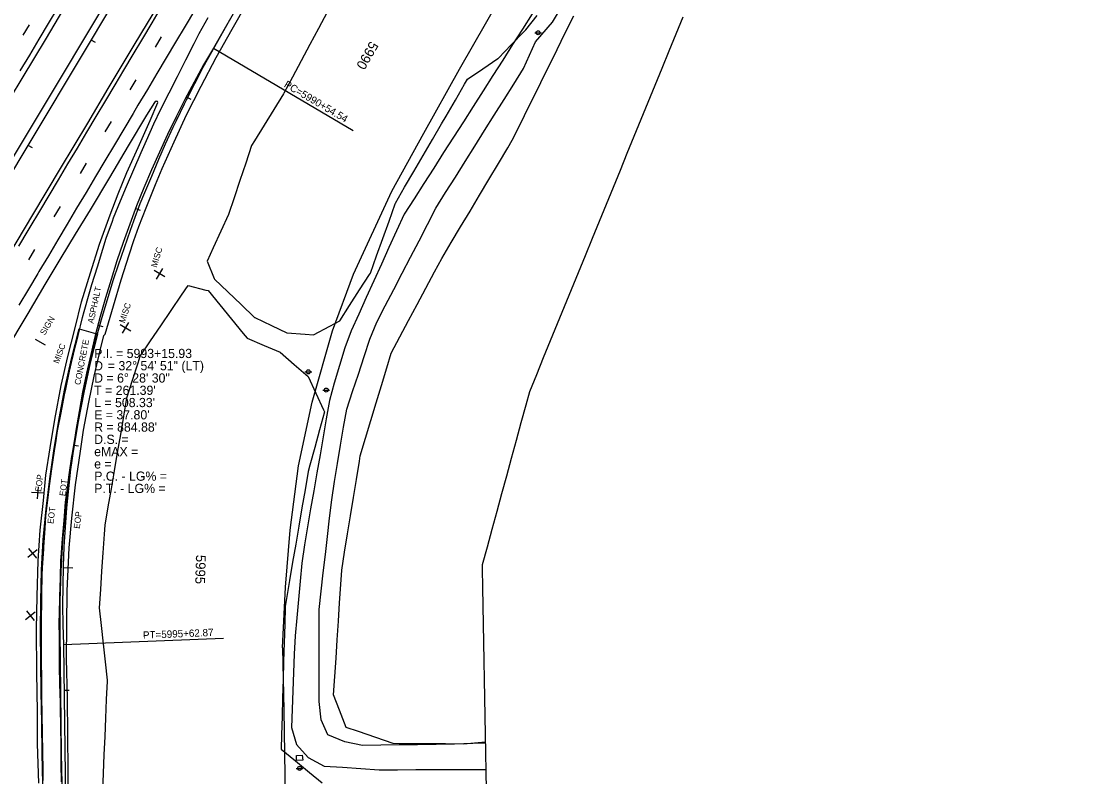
# Model space of a CAD drawing. Extents: x 2132221 to 2141942, y 535736 to 547298.
# Drawn here: x 2138929 to 2139793, y 541568 to 542184 of the extents above; entities that cross this region are included whole.
import ezdxf

# ---------------------------------------------------------------- set-up
doc = ezdxf.new("R2010")
doc.units = 0
for name, color, linetype in [('RD_EX_BldgApp', 7, 'Continuous'), ('RD_EX_BldgApp_txCode', 7, 'Continuous'), ('RD_EX_Conc', 7, 'Continuous'), ('RD_EX_Conc_txCode', 7, 'Continuous'), ('RD_EX_Driveway', 7, 'Continuous'), ('RD_EX_Fence_Other', 7, 'Continuous'), ('RD_EX_GuardRail', 7, 'Continuous'), ('RD_EX_Misc', 7, 'Continuous'), ('RD_EX_Misc_txCode', 7, 'Continuous'), ('RD_EX_Road', 7, 'Continuous'), ('RD_EX_Road_txCode', 7, 'Continuous'), ('RD_EX_SU_Pole', 7, 'Continuous'), ('RD_EX_VEG', 7, 'Continuous'), ('RD_HC_Cl', 7, 'Continuous'), ('RD_HC_Data', 7, 'Continuous'), ('RD_HC_Data_Tic', 7, 'Continuous'), ('RD_HC_TX_Sta50', 7, 'Continuous'), ('TOPO_E_TLIML-Line', 7, 'Continuous')]:
    doc.layers.add(name, color=color, linetype=linetype)

msp = doc.modelspace()

# ---------------------------------------------------------------- linework, layer by layer
at = {"layer": 'RD_EX_BldgApp'}
msp.add_line((2138939.91, 541924.37), (2138947.96, 541919.89), dxfattribs=at)
at = {"layer": 'RD_EX_Conc'}
for points in [[(2138964.17, 541884.13), (2138969.59, 541908.45), (2138975.68, 541932.7), (2138990.91, 541928.6)], [(2138979.79, 541880.98), (2138985.1, 541905.1), (2138990.91, 541928.6)], [(2138946.05, 541561.75), (2138945.51, 541586.82), (2138945.34, 541611.6), (2138944.81, 541636.66), (2138944.62, 541661.19), (2138944.29, 541686.45), (2138944.44, 541711.23), (2138945.21, 541736.04), (2138946.56, 541760.92), (2138948.83, 541786.03), (2138951.88, 541810.52), (2138955.41, 541835.19), (2138959.43, 541859.75), (2138964.17, 541884.13)], [(2138962.18, 541536.91), (2138961.81, 541562.08), (2138961.45, 541586.73), (2138961.09, 541611.67), (2138960.87, 541636.68), (2138960.43, 541661.54), (2138960.22, 541686.19), (2138960.39, 541710.97), (2138961.07, 541735.39), (2138962.56, 541759.82), (2138964.6, 541783.95), (2138967.59, 541808.74), (2138971.09, 541833.05), (2138975.3, 541857.21), (2138979.79, 541880.98)]]:
    msp.add_lwpolyline(points, dxfattribs=at)
at = {"layer": 'RD_EX_Driveway'}
for points in [[(2139307.02, 541595.19), (2139296.59, 541594.73), (2139281.59, 541594.29), (2139266.6, 541594.06), (2139251.6, 541593.84), (2139236.6, 541593.62), (2139221.6, 541593.39), (2139206.6, 541593.17), (2139192.23, 541596.25), (2139178.33, 541601.91), (2139172.94, 541614.14), (2139171.47, 541629.04), (2139171.47, 541644.04), (2139171.47, 541659.04), (2139171.47, 541674.04), (2139171.47, 541689.04), (2139171.47, 541704.04), (2139173.02, 541718.95), (2139174.71, 541733.86), (2139176.39, 541748.76), (2139178.07, 541763.67), (2139179.76, 541778.57), (2139181.57, 541793.46), (2139183.97, 541808.27), (2139186.38, 541823.07), (2139188.78, 541837.88), (2139191.18, 541852.68), (2139193.97, 541867.4), (2139198.62, 541881.66), (2139203.28, 541895.92), (2139207.94, 541910.18), (2139212.59, 541924.43), (2139218.36, 541938.21), (2139225.23, 541951.5), (2139232.11, 541964.78), (2139238.98, 541978.07), (2139245.85, 541991.36), (2139252.73, 542004.65), (2139259.6, 542017.94), (2139266.48, 542031.23), (2139274.4, 542043.86), (2139282.33, 542056.49), (2139290.26, 542069.12), (2139298.19, 542081.75), (2139306.12, 542094.38), (2139314.05, 542107.01), (2139321.98, 542119.64), (2139329.91, 542132.26), (2139337.88, 542144.97), (2139347.77, 542166.84), (2139361.62, 542182.78), (2139369.1, 542195.67)], [(2139345.05, 542189.57), (2139337.02, 542177), (2139328.99, 542164.44), (2139320.96, 542151.87), (2139312.89, 542139.23), (2139304.9, 542126.73), (2139296.87, 542114.16), (2139288.85, 542101.59), (2139280.77, 542088.95), (2139272.79, 542076.46), (2139264.76, 542063.89), (2139256.73, 542051.32), (2139248.7, 542038.75), (2139240.67, 542026.18), (2139234.37, 542012.68), (2139228.21, 541999.09), (2139222.06, 541985.5), (2139215.9, 541971.92), (2139209.74, 541958.33), (2139203.59, 541944.75), (2139197.43, 541931.16), (2139192.2, 541917.22), (2139187.9, 541902.94), (2139183.6, 541888.66), (2139179.7, 541874.28), (2139177.15, 541859.58), (2139174.6, 541844.88), (2139172.04, 541830.1), (2139169.5, 541815.48), (2139166.95, 541800.78), (2139164.4, 541786.08), (2139161.85, 541771.38), (2139159.3, 541756.68), (2139157.11, 541741.94), (2139155.79, 541727.08), (2139154.46, 541712.22), (2139153.14, 541697.36), (2139151.81, 541682.5), (2139151.07, 541667.6), (2139150.49, 541652.69), (2139149.9, 541637.79), (2139149.32, 541622.88), (2139148.74, 541607.97), (2139152.78, 541594.01), (2139162.33, 541583.33), (2139175.41, 541576.48), (2139190.34, 541575.45), (2139205.27, 541574.42), (2139220.2, 541573.47), (2139235.17, 541573.49), (2139250.13, 541573.51), (2139265.1, 541573.52), (2139280.06, 541573.54), (2139295.03, 541573.56), (2139307.41, 541573.57)]]:
    msp.add_lwpolyline(points, dxfattribs=at)
msp.add_lwpolyline([(2139153, 541585.04), (2139157.61, 541585.29), (2139158, 541581.37), (2139152.91, 541580.85)], close=True, dxfattribs=at)
at = {"layer": 'RD_EX_Fence_Other'}
for p, q in [((2139182.15, 541931.16), (2139199.29, 541977.5)), ((2139141.58, 541672.69), (2139143.91, 541722.32))]:
    msp.add_line(p, q, dxfattribs=at)
for points in [[(2139199.29, 541977.5), (2139230.66, 542044.92), (2139256.71, 542092.39), (2139285.74, 542144.4), (2139307.85, 542183.32), (2139338.4, 542236.88), (2139366.99, 542286.98), (2139396.2, 542337.99), (2139425.31, 542387.63), (2139459.61, 542447.78), (2139484.3, 542490.86), (2139507.59, 542531.82), (2139537.21, 542583.28), (2139570.34, 542640.33), (2139599.47, 542691.68), (2139623.24, 542733.3), (2139663.17, 542802.94), (2139685.76, 542843.79), (2139714.19, 542892.36), (2139738.8, 542935.51), (2139769.46, 542989.44), (2139792.81, 543030.29)], [(2139143.91, 541722.32), (2139147.81, 541768.77), (2139154.56, 541821.06), (2139165.57, 541873.11), (2139182.15, 541931.16)], [(2139141.58, 541672.69), (2139142.42, 541621.94), (2139143.3, 541569.08), (2139144.31, 541512.66), (2139145.95, 541449.43), (2139146.66, 541393.38), (2139147.22, 541353.23), (2139147.73, 541294.87), (2139148.66, 541239.78)]]:
    msp.add_lwpolyline(points, dxfattribs=at)
at = {"layer": 'RD_EX_GuardRail'}
msp.add_lwpolyline([(2138851.75, 541955.34), (2138865.25, 541977.82), (2138891.04, 542021.08), (2138921.51, 542071.79), (2138957.23, 542131.41), (2138984.41, 542176.81), (2139016.58, 542230.45), (2139056.94, 542297.59), (2139088.78, 542351.41), (2139113.89, 542392.68), (2139145.32, 542445.41), (2139147.37, 542448.82)], dxfattribs=at)
at = {"layer": 'RD_EX_Misc'}
for p, q in [((2138930.23, 542172.24), (2138935.22, 542180.63)), ((2139037.97, 542162.44), (2139042.97, 542170.82)), ((2139017.31, 542127.5), (2139022.3, 542135.88)), ((2138997.01, 542093.48), (2139002.01, 542101.86)), ((2138976.78, 542059.39), (2138981.77, 542067.78)), ((2138955.46, 542024.23), (2138960.46, 542032.62)), ((2138934.69, 541989.19), (2138939.68, 541997.58)), ((2139045.58, 541975.17), (2139036.99, 541980.29)), ((2139038.73, 541973.43), (2139043.84, 541982.03)), ((2139017.89, 541931.01), (2139009.3, 541936.13)), ((2139011.03, 541929.27), (2139016.15, 541937.87)), ((2138946.99, 541798.79), (2138937.02, 541799.52)), ((2138942.37, 541804.14), (2138941.64, 541794.17)), ((2138933.87, 541746.67), (2138941.64, 541752.96)), ((2138934.61, 541753.7), (2138940.9, 541745.93)), ((2138932.78, 541702.95), (2138939.07, 541695.18)), ((2138932.04, 541695.92), (2138939.81, 541702.21))]:
    msp.add_line(p, q, dxfattribs=at)
for points in [[(2138926.58, 542000.16), (2138934.32, 542013.01), (2138935.95, 542015.73), (2138943.63, 542028.61), (2138951.3, 542041.5), (2138958.98, 542054.39), (2138966.66, 542067.27), (2138974.34, 542080.16), (2138982.01, 542093.04), (2138989.69, 542105.93), (2138997.37, 542118.82), (2139005.05, 542131.7), (2139012.17, 542143.66), (2139019.86, 542156.54), (2139027.55, 542169.42), (2139035.24, 542182.3), (2139042.93, 542195.18)], [(2139069.74, 542192.36), (2139062.07, 542179.47), (2139054.39, 542166.58), (2139046.72, 542153.7), (2139039.05, 542140.81), (2139031.37, 542127.92), (2139023.7, 542115.03), (2139019.77, 542108.44), (2139012.1, 542095.55), (2139004.43, 542082.66), (2138996.75, 542069.77), (2138989.08, 542056.89), (2138981.4, 542044), (2138973.73, 542031.11), (2138966.06, 542018.22), (2138958.38, 542005.33), (2138950.71, 541992.44), (2138943.03, 541979.56), (2138942.08, 541977.95), (2138934.38, 541965.07), (2138926.68, 541952.2)], [(2138927.75, 542143.14), (2138935.45, 542156.01), (2138943.16, 542168.88), (2138950.86, 542181.75), (2138958.57, 542194.62)], [(2138946.46, 541564.7), (2138946.33, 541573.16), (2138946.11, 541588.16), (2138945.89, 541603.15), (2138945.67, 541618.15), (2138945.45, 541633.15), (2138945.23, 541648.15), (2138945.03, 541661.67), (2138945.09, 541676.67), (2138945.15, 541691.67), (2138945.16, 541695.74), (2138945.22, 541710.73), (2138945.24, 541716.8), (2138945.71, 541731.8), (2138945.91, 541738.23), (2138946.91, 541753.2), (2138947.04, 541755.13), (2138948.04, 541770.09), (2138948.73, 541780.51), (2138950.46, 541795.41), (2138951.54, 541804.77), (2138953.6, 541818.67), (2138955.79, 541833.51), (2138956.73, 541839.92), (2138958.16, 541849.59), (2138961.02, 541864.31), (2138963.87, 541879.04), (2138964.78, 541883.76), (2138967.92, 541898.43), (2138969.4, 541905.36), (2138973.02, 541919.92), (2138974.88, 541927.4), (2138978.49, 541941.95), (2138979.74, 541946.98), (2138983.94, 541961.38), (2138986.17, 541969.01), (2138990.61, 541983.34), (2138995.06, 541997.67), (2138997.83, 542006.61), (2139002.94, 542020.71), (2139003.85, 542023.22), (2139009.49, 542037.11), (2139014.3, 542048.96), (2139020.29, 542062.71), (2139026.27, 542076.47), (2139030.52, 542086.23), (2139036.75, 542099.88), (2139042.22, 542111.87), (2139049.03, 542125.24), (2139055.84, 542138.6), (2139062.65, 542151.97), (2139069.46, 542165.33), (2139073.59, 542173.45), (2139081, 542186.5)], [(2139098.25, 542184.44), (2139090.88, 542171.38), (2139083.51, 542158.32), (2139076.52, 542145.94), (2139069.76, 542132.55), (2139063.01, 542119.16), (2139061.32, 542115.82), (2139054.74, 542102.34), (2139052.1, 542096.91), (2139045.95, 542083.23), (2139040.4, 542070.87), (2139034.63, 542057.02), (2139029.01, 542043.55), (2139025.29, 542034.62), (2139020.16, 542020.52), (2139017.39, 542012.92), (2139012.46, 541998.75), (2139007.53, 541984.58), (2139003.42, 541972.77), (2138999.03, 541958.43), (2138998.46, 541956.58), (2138994.27, 541942.18), (2138990.07, 541927.78), (2138989.68, 541926.42), (2138985.93, 541911.9), (2138985.44, 541909.99), (2138984.06, 541903.55), (2138980.92, 541888.89), (2138977.77, 541874.22), (2138974.63, 541859.55), (2138974.58, 541859.3), (2138972.13, 541844.5), (2138969.67, 541829.7), (2138969.51, 541828.72), (2138967.48, 541813.86), (2138965.45, 541799), (2138964.44, 541791.63), (2138963.24, 541776.67), (2138962.04, 541761.72), (2138960.85, 541746.77), (2138960.67, 541744.57), (2138960.25, 541729.57), (2138959.83, 541714.58), (2138959.41, 541699.59), (2138959.27, 541694.69), (2138959.37, 541679.69), (2138959.47, 541664.69), (2138959.51, 541658.07), (2138959.88, 541643.08), (2138960.25, 541628.08), (2138960.36, 541623.53), (2138960.56, 541608.53), (2138960.75, 541593.53), (2138960.95, 541578.53), (2138961.15, 541563.53)]]:
    msp.add_lwpolyline(points, dxfattribs=at)
at = {"layer": 'RD_EX_Road'}
for points in [[(2139134.59, 542480.14), (2139117.82, 542452.18), (2139094.47, 542413.68), (2139071.14, 542374.55), (2139048.53, 542337.23), (2139029.44, 542304.84), (2139009.21, 542271.38), (2138989.73, 542238.46), (2138969.33, 542204.58), (2138948.78, 542169.73), (2138929.06, 542136.92), (2138909.7, 542105.48), (2138889.47, 542071.54), (2138872.98, 542043.32), (2138855.21, 542014.19), (2138826.2, 541965.96)], [(2138883.52, 541934.18), (2138898.95, 541960.2), (2138918.44, 541992.8), (2138938.06, 542025.7), (2138960.66, 542063.6), (2138982.75, 542100.59), (2138999.53, 542128.76), (2139020.67, 542163.95), (2139041.4, 542198.65), (2139058.21, 542226.76), (2139075.66, 542256.28), (2139095.39, 542289.29), (2139116.91, 542325.43), (2139138.66, 542361.84), (2139149.55, 542379.94), (2139189.43, 542446.45)], [(2138983.52, 541872.95), (2138987.95, 541894.18), (2138993.05, 541916.28), (2138995.99, 541927.43), (2138997.06, 541928.55), (2139003.71, 541951.47), (2139010.04, 541972.84), (2139016.64, 541993.01), (2139020.41, 542004.74), (2139024.43, 542016.16), (2139030.43, 542031.57), (2139037.92, 542050.5), (2139043.28, 542063.43), (2139053.3, 542085.18), (2139063.37, 542107.37), (2139075.11, 542130.56), (2139087.49, 542153.96), (2139100.38, 542177.02), (2139112.55, 542198.6)], [(2138961.04, 541886.58), (2138966.44, 541910.15), (2138972.39, 541933.76), (2138977.74, 541954.76), (2138985.08, 541978.5), (2138992.41, 542001.8), (2139001.05, 542025.73), (2139007.52, 542042.87), (2139014.62, 542060.2), (2139023.79, 542080.72), (2139033.53, 542102.69), (2139039.99, 542117.35), (2139039.63, 542118.01), (2139038.92, 542118.35), (2139038.25, 542118.23), (2139037.81, 542118.09), (2139037.03, 542117.37), (2139030.73, 542106.99), (2139015.73, 542082.05), (2139000.41, 542056.19), (2138984.72, 542029.95), (2138972.46, 542009.89), (2138960.85, 541990.72), (2138947.91, 541968.92), (2138933.88, 541945.35), (2138914.89, 541913.44)], [(2138942.81, 541562.51), (2138941.92, 541594.62), (2138941.79, 541620.58), (2138941.29, 541652.58), (2138940.94, 541688.02), (2138941.47, 541715.05), (2138942.48, 541743.85), (2138944.12, 541768.64), (2138946.75, 541793.03), (2138948.52, 541813.55), (2138952.01, 541835.89), (2138955.95, 541858.83), (2138961.04, 541886.58)], [(2138967.03, 541546.96), (2138966.77, 541573.19), (2138966.41, 541601.36), (2138966.19, 541631.68), (2138965.49, 541663.73), (2138965.59, 541691.38), (2138966, 541719.24), (2138967.51, 541754.21), (2138969.7, 541778.54), (2138972.69, 541805.74), (2138976.81, 541833.21), (2138979.18, 541850.2), (2138983.52, 541872.95)]]:
    msp.add_lwpolyline(points, dxfattribs=at)
at = {"layer": 'RD_EX_SU_Pole'}
for p, q in [((2139347.01, 542174.12), (2139352.51, 542174.12)), ((2139159.74, 541897.77), (2139165.24, 541897.77)), ((2139174.33, 541882.93), (2139179.83, 541882.93)), ((2139152.61, 541574.52), (2139158.11, 541574.52))]:
    msp.add_line(p, q, dxfattribs=at)
for centre in [(2139349.76, 542174.13), (2139162.5, 541897.78), (2139177.08, 541882.94), (2139155.36, 541574.53)]:
    msp.add_circle(centre, 1.65, dxfattribs=at)
at = {"layer": 'RD_EX_VEG'}
for points in [[(2139177.76, 542190.94), (2139170.69, 542177.71), (2139163.63, 542164.47), (2139156.56, 542151.24), (2139149.5, 542138.01), (2139142.43, 542124.78), (2139142.23, 542124.4), (2139134.39, 542111.61), (2139126.54, 542098.83), (2139118.7, 542086.05), (2139116.32, 542082.18), (2139111.55, 542067.96), (2139106.78, 542053.74), (2139102.01, 542039.52), (2139097.51, 542026.11), (2139091.31, 542012.46), (2139085.1, 541998.8), (2139080.15, 541987.9), (2139085.72, 541973.97), (2139086.03, 541973.2), (2139096.89, 541962.86), (2139107.76, 541952.52), (2139118.62, 541942.18), (2139118.88, 541941.94), (2139132.46, 541935.56), (2139145.05, 541929.65), (2139160.01, 541928.54), (2139166.69, 541928.04), (2139179.97, 541935.02), (2139188.06, 541939.27), (2139196.17, 541951.88), (2139204.29, 541964.49), (2139212.41, 541977.11), (2139213.16, 541978.28), (2139218.2, 541992.41), (2139223.24, 542006.54), (2139228.28, 542020.67), (2139233.32, 542034.79), (2139233.46, 542035.2), (2139241, 542048.16), (2139248.54, 542061.13), (2139256.09, 542074.1), (2139263.63, 542087.06), (2139271.17, 542100.03), (2139274.79, 542106.26), (2139282.34, 542119.23), (2139289.88, 542132.19), (2139292.2, 542136.19), (2139304.6, 542144.64), (2139317, 542153.08), (2139317.53, 542153.44), (2139327.92, 542164.27), (2139338.3, 542175.09), (2139339.66, 542176.5), (2139348.9, 542188.32)], [(2139307.01, 541595.83), (2139292.06, 541594.56), (2139289.25, 541594.32), (2139274.25, 541594.44), (2139259.25, 541594.57), (2139244.25, 541594.69), (2139231.76, 541594.79), (2139217.56, 541599.64), (2139203.37, 541604.49), (2139193.43, 541607.88), (2139188.03, 541621.88), (2139183.15, 541634.54), (2139184.11, 541649.51), (2139185.08, 541664.48), (2139186.04, 541679.45), (2139187.01, 541694.41), (2139187.97, 541709.38), (2139188.94, 541724.35), (2139189.69, 541736.02), (2139192.1, 541750.82), (2139194.51, 541765.63), (2139196.92, 541780.43), (2139199.33, 541795.24), (2139201.74, 541810.04), (2139204.15, 541824.85), (2139204.88, 541829.31), (2139209.21, 541843.67), (2139213.54, 541858.03), (2139217.87, 541872.39), (2139222.2, 541886.75), (2139226.53, 541901.12), (2139230.12, 541913.02), (2139237.18, 541926.25), (2139244.23, 541939.49), (2139251.29, 541952.73), (2139258.35, 541965.96), (2139265.4, 541979.2), (2139271.25, 541990.18), (2139278.94, 542003.06), (2139286.63, 542015.94), (2139294.32, 542028.82), (2139302, 542041.7), (2139309.69, 542054.58), (2139317.38, 542067.46), (2139325.06, 542080.34), (2139328.75, 542086.51), (2139335.38, 542099.96), (2139342.01, 542113.42), (2139348.64, 542126.87), (2139355.27, 542140.33), (2139361.9, 542153.78), (2139368.53, 542167.24), (2139375.16, 542180.69), (2139378.76, 542187.98)], [(2138994.95, 541555.66), (2138995.59, 541570.65), (2138996.24, 541585.63), (2138996.88, 541600.62), (2138997.53, 541615.6), (2138998.17, 541630.59), (2138998.81, 541645.58), (2138998.85, 541646.39), (2138997.19, 541661.29), (2138995.54, 541676.2), (2138993.89, 541691.11), (2138992.3, 541705.48), (2138993.33, 541720.44), (2138994.37, 541735.4), (2138995.41, 541750.37), (2138996.45, 541765.33), (2138996.97, 541772.82), (2138999.5, 541787.6), (2139002.03, 541802.39), (2139004.56, 541817.17), (2139007.09, 541831.96), (2139009.62, 541846.74), (2139012.15, 541861.53), (2139014.68, 541876.31), (2139014.73, 541876.63), (2139019.32, 541890.91), (2139023.91, 541905.19), (2139025.61, 541910.5), (2139034.01, 541922.93), (2139042.41, 541935.36), (2139050.81, 541947.79), (2139059.2, 541960.22), (2139064.61, 541968.22), (2139079.12, 541964.41), (2139080.9, 541963.94), (2139090.41, 541952.34), (2139099.91, 541940.73), (2139109.41, 541929.13), (2139112.68, 541925.14), (2139126.49, 541919.29), (2139139.66, 541913.71), (2139150.97, 541903.86), (2139162.29, 541894), (2139162.37, 541893.93), (2139168.67, 541880.32), (2139174.97, 541866.71), (2139175.72, 541865.07), (2139171.75, 541850.61), (2139167.78, 541836.14), (2139163.81, 541821.68), (2139162.37, 541816.44), (2139159.84, 541801.65), (2139157.32, 541786.87), (2139154.79, 541772.08), (2139152.27, 541757.3), (2139149.75, 541742.51), (2139147.22, 541727.72), (2139144.7, 541712.94), (2139143.67, 541706.9), (2139143.25, 541691.91), (2139142.82, 541676.91), (2139142.4, 541661.92), (2139141.98, 541646.92), (2139141.56, 541631.93), (2139141.14, 541616.93), (2139140.72, 541601.94), (2139140.39, 541590.19), (2139151.99, 541580.67), (2139163.58, 541571.16), (2139173.7, 541562.86)]]:
    msp.add_lwpolyline(points, dxfattribs=at)
at = {"layer": 'RD_HC_Cl'}
for p, q in [((2139719.79, 543396.28), (2136851.48, 538600.7)), ((2139161.85, 542295.9), (2139085.2, 542161.71)), ((2138963.01, 541675.46), (2138981.93, 540244.3))]:
    msp.add_line(p, q, dxfattribs=at)
msp.add_arc((2139847.14, 541711.76), 884.88, 149.43694, 182.35111, dxfattribs=at)
at = {"layer": 'RD_HC_Data'}
for p, q in [((2139085.2, 542161.71), (2139198.98, 542094.52)), ((2138963.01, 541675.46), (2139093.27, 541680.81))]:
    msp.add_line(p, q, dxfattribs=at)
at = {"layer": 'RD_HC_Data_Tic'}
for p, q in [((2138985.38, 542168.4), (2138988.81, 542166.35)), ((2139063.1, 542121.99), (2139066.64, 542120.13)), ((2138934.05, 542082.58), (2138937.48, 542080.53)), ((2139021.84, 542030.95), (2139025.57, 542029.51)), ((2138991.11, 541935.85), (2138994.98, 541934.84)), ((2138971.3, 541837.89), (2138975.26, 541837.32)), ((2138962.66, 541738.31), (2138970.66, 541738.07)), ((2138963.5, 541638.33), (2138967.5, 541638.38))]:
    msp.add_line(p, q, dxfattribs=at)
at = {"layer": 'TOPO_E_TLIML-Line'}
msp.add_lwpolyline([(2139307.7, 541557.13), (2139307.43, 541572.13), (2139307.17, 541587.13), (2139306.9, 541602.12), (2139306.63, 541617.12), (2139306.37, 541632.12), (2139306.1, 541647.12), (2139305.84, 541662.11), (2139305.57, 541677.11), (2139305.3, 541692.11), (2139305.04, 541707.11), (2139304.77, 541722.11), (2139304.51, 541737.1), (2139304.44, 541740.71), (2139308.39, 541755.18), (2139312.34, 541769.65), (2139316.3, 541784.12), (2139320.25, 541798.59), (2139324.2, 541813.06), (2139328.15, 541827.53), (2139332.1, 541842), (2139336.05, 541856.47), (2139340, 541870.94), (2139342.93, 541881.65), (2139348.61, 541895.53), (2139354.29, 541909.42), (2139359.97, 541923.3), (2139365.65, 541937.18), (2139371.34, 541951.06), (2139377.02, 541964.94), (2139382.7, 541978.83), (2139388.38, 541992.71), (2139394.06, 542006.59), (2139399.75, 542020.47), (2139405.43, 542034.36), (2139411.11, 542048.24), (2139416.79, 542062.12), (2139422.47, 542076), (2139428.16, 542089.88), (2139433.84, 542103.77), (2139439.52, 542117.65), (2139445.2, 542131.53), (2139450.88, 542145.41), (2139456.57, 542159.29), (2139462.25, 542173.18), (2139467.93, 542187.06)], dxfattribs=at)

# ---------------------------------------------------------------- texts
at = {"layer": 'RD_EX_BldgApp_txCode'}
msp.add_text('SIGN', height=5, rotation=59.23746, dxfattribs=at).set_placement((2138947.78, 541927.15))
at = {"layer": 'RD_EX_Conc_txCode'}
msp.add_text('CONCRETE', height=5, rotation=79.04434, dxfattribs=at).set_placement((2138976.74, 541886.74))
at = {"layer": 'RD_EX_Misc_txCode'}
for s, rotation, p in [(' MISC', 73.28154, (2139038.39, 541980.68)), (' MISC', 71.33904, (2139012.22, 541935.4)), (' MISC', 69.54817, (2138958.46, 541902.3)), ('EOT', 82.87199, (2138964.58, 541796.27)), ('EOT', 82.87199, (2138954.78, 541773.65))]:
    msp.add_text(s, height=5, rotation=rotation, dxfattribs=at).set_placement(p)
at = {"layer": 'RD_EX_Road_txCode'}
for s, rotation, p in [('ASPHALT', 77.92181, (2138987.43, 541936.82)), ('EOP', 83.13663, (2138944.83, 541799.81)), ('EOP', 83.13663, (2138976.24, 541769.65))]:
    msp.add_text(s, height=5, rotation=rotation, dxfattribs=at).set_placement(p)
at = {"layer": 'RD_HC_Data'}
for s, rotation, p in [('PC=5990+54.54', 329.43694, (2139142.18, 542130.38)), ('PT=5995+62.87', 2.35111, (2139027.87, 541680.12))]:
    msp.add_text(s, height=6, rotation=rotation, dxfattribs=at).set_placement(p)
for s, p in [('P.I. = 5993+15.93', (2138988, 541909)), ('D', (2138988, 541899)), ('    = 32%%d 54\' 51" (LT)', (2138988, 541899)), ('D = 6%%d 28\' 30"', (2138988, 541889)), ("T = 261.39'", (2138988, 541879)), ("L = 508.33'", (2138988, 541869)), ("E = 37.80'", (2138988, 541859)), ("R = 884.88'", (2138988, 541849)), ('D.S. = ', (2138988, 541839)), ('eMAX = ', (2138988, 541829)), ('e = ', (2138988, 541819)), ('P.C. - LG% = ', (2138988, 541809)), ('P.T. - LG% = ', (2138988, 541799))]:
    msp.add_text(s, height=7.5, dxfattribs=at).set_placement(p)
at = {"layer": 'RD_HC_TX_Sta50'}
for s, rotation, p in [('5990', 240.26572, (2139213.09, 542167.87)), ('5995', 268.2803, (2139071.02, 541748.68))]:
    msp.add_text(s, height=8, rotation=rotation, dxfattribs=at).set_placement(p)

doc.saveas('drawing.dxf')
